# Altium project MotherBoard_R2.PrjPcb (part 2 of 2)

## Sheet powerSupplyAndMontior_r1.SchDoc
size A3; Date: Not shown in title block; ApprovedBy: Not shown in title block; CheckedBy: Not shown in title block; Author: Not shown in title block; CompanyName: Not shown in title block; Engineer: Not shown in title block; Organization: Not shown in title block; Address1: Not shown in title block; Address2: Not shown in title block; Address3: Not shown in title block; Address4: Not shown in title block; DocumentNumber: 2; Revision: Use project parameter SCH_Rev; SheetNumber: 2; SheetTotal: 3; PageSetup: Record=PageOptions¦CenterHorizontal=True¦CenterVertical=True¦PrintScale=1.00¦XCorrection=1.00¦YCorrection=1.00¦PrintKind=0¦BorderSize=5000000¦LeftOffset=0¦BottomOffset=0¦Orientation=2¦PaperLength=1000¦PaperWidth=1000¦Scale=100¦PaperSource=15¦PrintQuality=600¦MediaType=1¦DitherType=10¦PaperKind=Letter¦PrintScaleMode=1
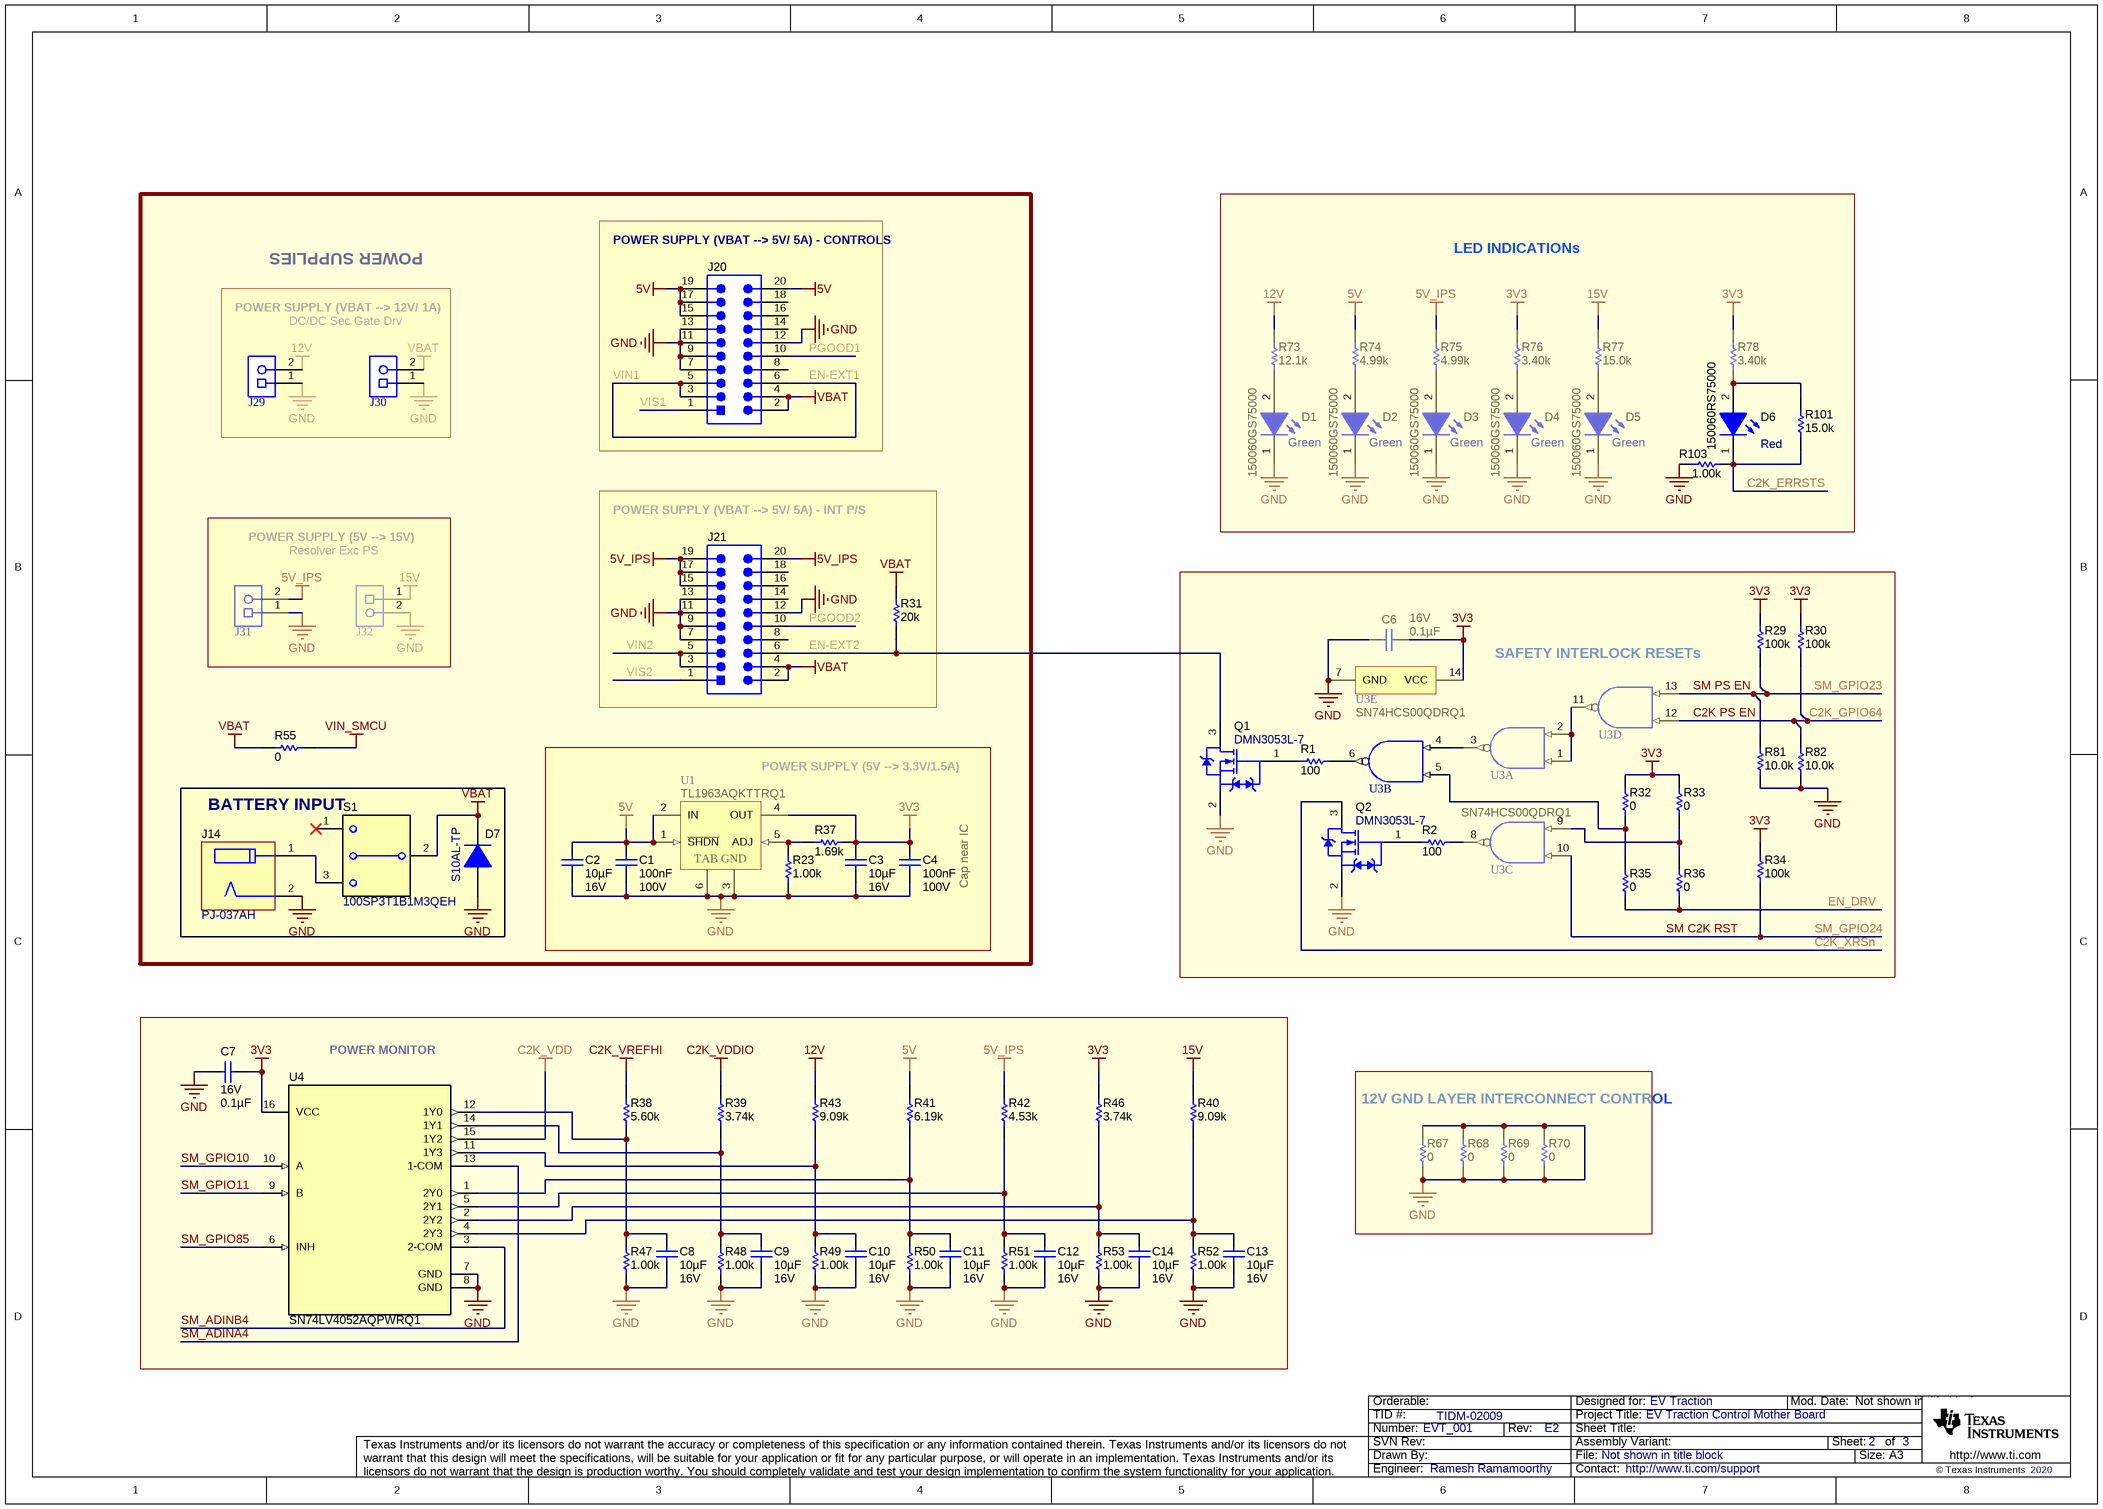
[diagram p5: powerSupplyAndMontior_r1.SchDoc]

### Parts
C1  Cap_F: 100nF  VDC_V: 100V  [0805_HV]  (hidden comment: C2012X7R2A104K125AA)
C2  ValueDisplayed: 10µF  VDC_V: 16V  [0805_HV]  (hidden comment: GRM21BR61C106KE15K)
C3  ValueDisplayed: 10µF  VDC_V: 16V  [0805_HV]  (hidden comment: GRM21BR61C106KE15K)
C4  Cap_F: 100nF  VDC_V: 100V  [0805_HV]  (hidden comment: C2012X7R2A104K125AA)
C6  VDC_V: 16V  ValueDisplayed: 0.1µF  [1206]  (hidden comment: 1206YC104KAT2A)
C7  VDC_V: 16V  ValueDisplayed: 0.1µF  [1206]  (hidden comment: 1206YC104KAT2A)
C8  ValueDisplayed: 10µF  VDC_V: 16V  [0805_HV]  (hidden comment: GRM21BR61C106KE15K)
C9  ValueDisplayed: 10µF  VDC_V: 16V  [0805_HV]  (hidden comment: GRM21BR61C106KE15K)
C10  ValueDisplayed: 10µF  VDC_V: 16V  [0805_HV]  (hidden comment: GRM21BR61C106KE15K)
C11  ValueDisplayed: 10µF  VDC_V: 16V  [0805_HV]  (hidden comment: GRM21BR61C106KE15K)
C12  ValueDisplayed: 10µF  VDC_V: 16V  [0805_HV]  (hidden comment: GRM21BR61C106KE15K)
C13  ValueDisplayed: 10µF  VDC_V: 16V  [0805_HV]  (hidden comment: GRM21BR61C106KE15K)
C14  ValueDisplayed: 10µF  VDC_V: 16V  [0805_HV]  (hidden comment: GRM21BR61C106KE15K)
D1  150060GS75000  value Green  [WL-SMCW_GREEN]
D2  150060GS75000  value Green  [WL-SMCW_GREEN]
D3  150060GS75000  value Green  [WL-SMCW_GREEN]
D4  150060GS75000  value Green  [WL-SMCW_GREEN]
D5  150060GS75000  value Green  [WL-SMCW_GREEN]
D6  150060RS75000  value Red  [WL-SMCW_RED]
D7  S10AL-TP  [SMC_265]
J14  PJ-037AH  [CUI_PJ-037AH]
J20  SBH11-PBPC-D10-ST-BK  [Sullins_SBH11-xxxC-D10-ST]  (value not drawn)
J21  SBH11-PBPC-D10-ST-BK  [Sullins_SBH11-xxxC-D10-ST]  (value not drawn)
J29  5-534206-1  [CONN_534206-1]  (value not drawn)
J30  5-534206-1  [CONN_534206-1]  (value not drawn)
J31  5-534206-1  [CONN_534206-1]  (value not drawn)
J32  5-534206-1  [CONN_534206-1]  (value not drawn)
Q1  DMN3053L-7  [SOT-23]
Q2  DMN3053L-7  [SOT-23]
R1  ValueDisplayed: 100  [0603]  (hidden comment: CRCW0603100RFKEA)
R2  ValueDisplayed: 100  [0603]  (hidden comment: CRCW0603100RFKEA)
R23  ValueDisplayed: 1.00k  [0805_HV]  (hidden comment: ERJ-P06F1001V)
R29  ValueDisplayed: 100k  [0805_HV]  (hidden comment: RT0805BRD07100KL)
R30  ValueDisplayed: 100k  [0805_HV]  (hidden comment: RT0805BRD07100KL)
R31  ValueDisplayed: 20k  [0805_HV]  (hidden comment: ERJ-6GEYJ203V)
R32  ValueDisplayed: 0  [0805_HV]  (hidden comment: ERJ-6GEY0R00V)
R33  ValueDisplayed: 0  [0805_HV]  (hidden comment: ERJ-6GEY0R00V)
R34  ValueDisplayed: 100k  [0805_HV]  (hidden comment: RT0805BRD07100KL)
R35  ValueDisplayed: 0  [0805_HV]  (hidden comment: ERJ-6GEY0R00V)
R36  ValueDisplayed: 0  [0805_HV]  (hidden comment: ERJ-6GEY0R00V)
R37  ValueDisplayed: 1.69k  [0805_HV]  (hidden comment: ERJ-6ENF1691V)
R38  ValueDisplayed: 5.60k  [0805_HV]  (hidden comment: RR1220P-562-D)
R39  ValueDisplayed: 3.74k  [0805_HV]  (hidden comment: RR1220P-3741-D-M)
R40  ValueDisplayed: 9.09k  [0805_HV]  (hidden comment: ERJ-6ENF9091V)
R41  ValueDisplayed: 6.19k  [0805_HV]  (hidden comment: ERJ-6ENF6191V)
R42  ValueDisplayed: 4.53k  [0805_HV]  (hidden comment: RR1220P-4531-D-M)
R43  ValueDisplayed: 9.09k  [0805_HV]  (hidden comment: ERJ-6ENF9091V)
R46  ValueDisplayed: 3.74k  [0805_HV]  (hidden comment: RR1220P-3741-D-M)
R47  ValueDisplayed: 1.00k  [0805_HV]  (hidden comment: ERJ-P06F1001V)
R48  ValueDisplayed: 1.00k  [0805_HV]  (hidden comment: ERJ-P06F1001V)
R49  ValueDisplayed: 1.00k  [0805_HV]  (hidden comment: ERJ-P06F1001V)
R50  ValueDisplayed: 1.00k  [0805_HV]  (hidden comment: ERJ-P06F1001V)
R51  ValueDisplayed: 1.00k  [0805_HV]  (hidden comment: ERJ-P06F1001V)
R52  ValueDisplayed: 1.00k  [0805_HV]  (hidden comment: ERJ-P06F1001V)
R53  ValueDisplayed: 1.00k  [0805_HV]  (hidden comment: ERJ-P06F1001V)
R55  ValueDisplayed: 0  [0805_HV]  (hidden comment: ERJ-6GEY0R00V)
R67  ValueDisplayed: 0  [0805_HV]  (hidden comment: ERJ-6GEY0R00V)
R68  ValueDisplayed: 0  [0805_HV]  (hidden comment: ERJ-6GEY0R00V)
R69  ValueDisplayed: 0  [0805_HV]  (hidden comment: ERJ-6GEY0R00V)
R70  ValueDisplayed: 0  [0805_HV]  (hidden comment: ERJ-6GEY0R00V)
R73  ValueDisplayed: 12.1k  [0805_HV]  (hidden comment: ERJ-6ENF1212V)
R74  ValueDisplayed: 4.99k  [0805_HV]  (hidden comment: ERJ-6ENF4991V)
R75  ValueDisplayed: 4.99k  [0805_HV]  (hidden comment: ERJ-6ENF4991V)
R76  ValueDisplayed: 3.40k  [0805_HV]  (hidden comment: ERJ-6ENF3401V)
R77  ValueDisplayed: 15.0k  [0805_HV]  (hidden comment: CRCW080515K0FKEA)
R78  ValueDisplayed: 3.40k  [0805_HV]  (hidden comment: ERJ-6ENF3401V)
R81  ValueDisplayed: 10.0k  [0805_HV]  (hidden comment: RR1220P-103-D)
R82  ValueDisplayed: 10.0k  [0805_HV]  (hidden comment: RR1220P-103-D)
R101  ValueDisplayed: 15.0k  [0805_HV]  (hidden comment: CRCW080515K0FKEA)
R103  ValueDisplayed: 1.00k  [0805_HV]  (hidden comment: ERJ-P06F1001V)
S1  100SP3T1B1M3QEH  [SW_100SP3T1B1M3QEH]
U1  TL1963AQKTTRQ1  [KTT0005A_N]
U3  SN74HC00QDRG4Q1  [D0014A_N]  (value not drawn)  (parts A,B,C,D,E of 5)
U4  SN74LV4052AQPWRQ1  [PW0016A_N]

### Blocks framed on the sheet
POWER SUPPLIES: C1-C4 J29-J32 R23 R37 R55 U1
POWER SUPPLY (VBAT --> 5V/ 5A) - CONTROLS: J20
LED INDICATIONs: D1-D6 R73-R78 R101 R103
POWER SUPPLY (VBAT --> 5V/ 5A) - INT P/S: J21 R31
SAFETY INTERLOCK RESETs: C6 Q1 Q2 R1 R2 R29 R30 R32-R36 R81 R82 U3
BATTERY INPUT: D7 J14 S1
POWER MONITOR: C7-C14 R38-R43 R46-R53 U4
12V GND LAYER INTERCONNECT CONTROL: R67-R70

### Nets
3V3: C3.2 C4.1 C6.2 C7.1 R29.2 R30.2 R32.2 R33.2 R34.2 R37.1 R46.2 R76.2 R78.2 U1.4(OUT) U3.14(VCC) U4.16(VCC)
5V: C1.1 C2.1 J20.15 J20.17 J20.19 J20.20 R41.2 R74.2 U1.1(~{SHDN}) U1.2(IN)
5V_IPS: J21.15 J21.17 J21.19 J21.20 J31.2 R42.2 R75.2
12V: J29.2 R43.2 R73.2
15V: J32.1 R40.2 R77.2
C2K_VDD: U4.15(1Y2)
C2K_VDDIO: R39.2
C2K_VREFHI: R38.2
GND: C1.2 C2.2 C3.1 C4.2 C6.1 C7.2 C8.1 C9.1 C10.1 C11.1 C12.1 C13.1 C14.1 D1.1(K) D2.1(K) D3.1(K) D4.1(K) D5.1(K) D7.2(A) J14.2 J20.7 J20.9 J20.11 J20.12 J20.13 J21.7 J21.9 J21.11 J21.12 J21.13 J29.1 J30.1 J31.1 J32.2 Q1.2(S) Q2.2(S) R23.1 R47.1 R48.1 R49.1 R50.1 R51.1 R52.1 R53.1 R67.1 R67.2 R68.1 R68.2 R69.1 R69.2 R70.1 R70.2 R81.1 R82.1 R103.2 U1.3(GND) U1.6(TAB) U3.7(GND) U4.7(GND) U4.8(GND)
VBAT: D7.1(K) J20.2 J20.4 J21.2 J21.4 J30.2 R31.2 R55.1 S1.2(COM)
VIN_SMCU: R55.2
C2K PS EN: R30.1 R82.2 U3.12(4A)  [also labelled C2K_GPIO64]
C2K_ERRSTS: D6.1(K) R101.1 R103.1
C2K_XRSn: Q2.3(D)
EN-EXT1: J20.3 J20.5 J20.6  [also labelled VIN1]
EN-EXT2: J21.6 Q1.3(D) R31.1
EN_DRV: R35.1 R36.1
PGOOD1: J20.10
PGOOD2: J21.10
SM C2K RST: R34.1 U3.10(3B)  [also labelled SM_GPIO24]
SM PS EN: R29.1 R81.2 U3.13(4B)  [also labelled SM_GPIO23]
SM_ADINA4: U4.13(1-COM)
SM_ADINB4: U4.3(2-COM)
SM_GPIO10: U4.10(A)
SM_GPIO11: U4.9(B)
SM_GPIO85: U4.6(INH)
VIN2: J21.3 J21.5
VIS1: J20.1
VIS2: J21.1
NetC8_2: C8.2 R38.1 R47.2 U4.12(1Y0)
NetC9_2: C9.2 R39.1 R48.2 U4.14(1Y1)
NetC10_2: C10.2 R43.1 R49.2 U4.11(1Y3)
NetC11_2: C11.2 R41.1 R50.2 U4.1(2Y0)
NetC12_2: C12.2 R42.1 R51.2 U4.5(2Y1)
NetC13_2: C13.2 R40.1 R52.2 U4.4(2Y3)
NetC14_2: C14.2 R46.1 R53.2 U4.2(2Y2)
NetD1_2: D1.2(A) R73.1
NetD2_2: D2.2(A) R74.1
NetD3_2: D3.2(A) R75.1
NetD4_2: D4.2(A) R76.1
NetD5_2: D5.2(A) R77.1
NetD6_2: D6.2(A) R78.1 R101.2
NetJ14_1: J14.1 S1.3
NetQ1_1: Q1.1(G) R1.1
NetQ2_1: Q2.1(G) R2.1
NetR1_2: R1.2 U3.6(2Y)
NetR2_2: R2.2 U3.8(3Y)
NetR23_2: R23.2 R37.2 U1.5(ADJ)
NetR32_1: R32.1 R35.2 U3.5(2B)
NetR33_1: R33.1 R36.2 U3.9(3A)
NetU3_1: U3.1(1A) U3.2(1B) U3.11(4Y)
NetU3_3: U3.3(1Y) U3.4(2A)

Not connected (* = marked no-connect by the designer): J20 8 14 16 18; J21 8 14 16 18; S1 1*

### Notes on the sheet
- POWER SUPPLY (VBAT --> 12V/ 1A)
- DC/DC Sec Gate Drv
- POWER SUPPLY (5V --> 15V)
- Resolver Exc PS
- (near U1) POWER SUPPLY (5V --> 3.3V/1.5A)
- (near C4) Cap near IC

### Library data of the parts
C1 C4 = CMP-0007886-2: CAP, CERM, 0.1 uF, 100 V, +/- 10%, X7R, 0805; Manufacturer: TDK; TaMin_C: -55°C; ESR_ohm: 0.020726; Polarized: N; SizeAreaWB_mm2: 6.75; Value1: 0.020726 ohm; U/M: EA; Value: 0.1uF; TaMax_C: 125°C; SizeZ_mm: 1.45; SizeX_mm: 2; SizeY_mm: 1.25; Cap_Case: 0805; SizeArea_mm2: 2.5; IRMS_A: 1.456A; AEC Category: Q200
C2 C3 C8-C14 = CMP-0086228-1: CAP, CERM, 10 µF, 16 V,+/- 10%, X5R, 0805; Manufacturer: MuRata; Green_REACh: Incomplete; TaMax_C: 85°C; Value: 10uF; Green_Lifecycle: Active; AEC Qualified: N; SizeY_mm: 1.25; SizeX_mm: 2; AEC Category: Q200; Cap_Case: 0805; SizeArea_mm2: 2.5; SizeAreaWB_mm2: 6.75; SizeZ_mm: 1.45; TaMin_C: -55°C; U/M: EA
C6 C7 = CMP-0860522-1: CAP, CERM, 0.1 µF, 16 V,+/- 10%, X7R, 1206; Manufacturer: AVX; SizeArea_mm2: 5.12; SizeX_mm: 3.2; Value: 0.1uF; SizeAreaWB_mm2: 10.92; Cap_F: 100nF; SizeZ_mm: 1.35; AEC Category: Q200; Polarized: N; U/M: EA; SizeY_mm: 1.6; TaMin_C: -55°C; TaMax_C: 125°C
D1-D5 = CMP-0002905-2: LED, Green, SMD; Manufacturer: Wurth Elektronik; Type: InGaN; Vf_V: 3.2V; Io_A: 20mA; Tjmax_C: 85°C; Value1: W; Angle: 140
D6 = CMP-0002947-3: LED, Red, SMD; Manufacturer: Wurth Elektronik; Value1: 0.072W; Vf_V: 2V; Angle: 140; Tjmax_C: 85°C; Type: AlInGaP; Vr_V: 5V; Io_A: 30mA; Power_TotalModule: 72mW
D7 = CMP-0077511-1: Diode, Standard Recovery Rectifier, 50 V, 10 A, SMC; Manufacturer: Micro Commercial Components; SizeAreaWB_mm2: 78.5757; Vr_V: 50V; SizeArea_mm2: 46.8857; AEC Qualified: N; AEC Category: Q101; Value: 50V; SizeZ_mm: 2.62; Io_A: 10A; Vf_V: 1.2V; SizeY_mm: 5.905; U/M: EA; SizeX_mm: 7.94
J14 = CMP-0075114-1: Power Jack, 2mm, R/A, TH; Manufacturer: CUI Inc.; CNHeader: False; Shrouded: N; Gender: Male; Row_Count: 1; Pitch_mm: 6
J20 J21 = CMP-0054720-2: Header (Shrouded), 2.54mm, 10x2, Gold, Black, TH; Manufacturer: Sullins Connector Solutions; Current_A: 3A; Green_Lifecycle: Not Set; Shrouded: Y; Gender: Male; Green_REACh: Incomplete; Voltage_V: 1kV; Row_Count: 2; RowSpacing_mm: 2.54
J29-J32 = CMP-0054836-1: Connector, Receptacle, 100mil, 2x1, Gold plated, TH; Manufacturer: TE Connectivity; CNHeader: FALSE; Green_Lifecycle: Active; Green_REACh: Passed
Q1 Q2 = CMP-0000613-1: MOSFET, N-CH, 30 V, 4 A, AEC-Q101, SOT-23; Alternate Manufacturer: None; Manufacturer: Diodes Inc.; SizeZ_mm: 1.1; ChType: N; Value2: 7.3 nC; Value1: 0; VdsMax_V: 30V; SizeX_mm: 2.5; SizeY_mm: 3; Vgs_V: 12V; AEC Qualified: Y; Value: 30V; Rdson45_ohm: 0.05; SizeArea_mm2: 7.5; AEC Category: Q101; IdsMax_A: 4A; SizeAreaWB_mm2: 14; U/M: EA; QgTyp_nC: 7.3
R1 R2 = CMP-0021991-4: RES, 100, 1%, 0.1 W, AEC-Q200 Grade 0, 0603; Manufacturer: Vishay-Dale; Power_W: 100mW; TempCo: 100 ppm/C; Value_Code: 100R; Value: 100; EIA_Code: E96; SizeX_mm: 1.6; SizeY_mm: 0.8; SizeZ_mm: 1; Value2: 0.1W; SizeArea_mm2: 1.28; AEC Qualified: Y; VDC_V: 75V; AEC Category: Q200; AEC Grade: 0
R23 R47-R53 R103 = CMP-0021848-2: RES, 1.00 k, 1%, 0.25 W, 0805; Manufacturer: Panasonic; Power_W: 250mW; TempCo: 100 ppm/C; Value_Code: 1k00; U/M: EA; Value: 1.00k; EIA_Code: E96; Res_ohm: 1k; SizeX_mm: 2; SizeY_mm: 1.25; SizeZ_mm: 1.45; Value2: 0.25W; SizeArea_mm2: 2.5; VDC_V: 400V; AEC Category: Q200
R29 R30 R34 = CMP-0019441-2: RES, 100 k, 0.1%, 0.125 W, 0805; Manufacturer: Yageo America; Power_W: 125mW; TempCo: 25 ppm/C; U/M: EA; Value: 100k; EIA_Code: E192; SizeX_mm: 2; SizeY_mm: 1.25; SizeZ_mm: 1.45; Value2: 0.125W; SizeArea_mm2: 2.5; VDC_V: 150V; AEC Category: Q200
R31 = CMP-0020671-1: RES, 20 k, 5%, 0.125 W, 0805; Manufacturer: Panasonic; Power_W: 125mW; TempCo: 200 ppm/C; Value_Code: 20k0; U/M: EA; Value: 20k; EIA_Code: E24; SizeX_mm: 2; SizeY_mm: 1.25; SizeZ_mm: 1.45; Value2: 0.125W; SizeArea_mm2: 2.5; VDC_V: 150V; AEC Category: Q200
R32 R33 R35 R36 R55 R67-R70 = CMP-0020616-3: RES, 0, 5%, 0.125 W, AEC-Q200 Grade 0, 0805; Manufacturer: Panasonic; Power_W: 125mW; TempCo: 600 ppm/C; Value_Code: 0000; Value: 0; EIA_Code: E24; SizeX_mm: 2; SizeY_mm: 1.25; SizeZ_mm: 1.45; Value2: 0.125W; SizeArea_mm2: 2.5; AEC Qualified: Y; VDC_V: 150V; AEC Category: Q200; SizeAreaWB_mm2: 6.75
R37 = CMP-0021591-3: RES, 1.69 k, 1%, 0.125 W, AEC-Q200 Grade 0, 0805; Manufacturer: Panasonic; Power_W: 125mW; TempCo: 100 ppm/C; Value_Code: 1k69; Value: 1.69k; EIA_Code: E96; SizeX_mm: 2; SizeY_mm: 1.25; SizeZ_mm: 1.45; Value2: 0.125W; SizeArea_mm2: 2.5; AEC Qualified: Y; AEC Category: Q200; AEC Grade: 0; SizeAreaWB_mm2: 6.75
R38 = CMP-0019324-1: RES, 5.60 k, 0.5%, 0.1 W, 0805; Manufacturer: Susumu Co Ltd; Power_W: 100mW; TempCo: 25 ppm/C; Value_Code: 5k60; U/M: EA; Value: 5.60k; Res_ohm: 5.6k; SizeX_mm: 2; SizeY_mm: 1.25; SizeZ_mm: 1.45; Value2: 0.1W; SizeArea_mm2: 2.5; VDC_V: 100V; AEC Category: Q200
R39 R46 = CMP-0019268-2: RES, 3.74 k, 0.5%, 0.1 W, 0805; Manufacturer: Susumu Co Ltd; Power_W: 100mW; TempCo: 25 ppm/C; Value_Code: 3k74; U/M: EA; Value: 3.74k; EIA_Code: E192; SizeX_mm: 2; SizeY_mm: 1.25; SizeZ_mm: 1.45; Value2: 0.1W; SizeArea_mm2: 2.5; VDC_V: 100V; AEC Category: Q200
R40 R43 = CMP-0021809-3: RES, 9.09 k, 1%, 0.125 W, AEC-Q200 Grade 0, 0805; Manufacturer: Panasonic; Power_W: 125mW; TempCo: 100 ppm/C; Value_Code: 9k09; Value: 9.09k; EIA_Code: E96; SizeX_mm: 2; SizeY_mm: 1.25; SizeZ_mm: 1.45; Value2: 0.125W; SizeArea_mm2: 2.5; AEC Qualified: Y; AEC Category: Q200; AEC Grade: 0; SizeAreaWB_mm2: 6.75
R41 = CMP-0021761-3: RES, 6.19 k, 1%, 0.125 W, AEC-Q200 Grade 0, 0805; Manufacturer: Panasonic; Value: 6.19k; EIA_Code: E96; SizeX_mm: 2; SizeY_mm: 1.25; SizeZ_mm: 1.45; Value2: 0.125W; SizeArea_mm2: 2.5; AEC Qualified: Y; AEC Category: Q200; AEC Grade: 0; Power_W: 125mW; TempCo: 100 ppm/C; Value_Code: 6k19; SizeAreaWB_mm2: 6.75
R42 = CMP-0019292-2: RES, 4.53 k, 0.5%, 0.1 W, 0805; Manufacturer: Susumu Co Ltd; Power_W: 100mW; TempCo: 25 ppm/C; Value_Code: 4k53; U/M: EA; Value: 4.53k; EIA_Code: E192; SizeX_mm: 2; SizeY_mm: 1.25; SizeZ_mm: 1.45; Value2: 0.1W; SizeArea_mm2: 2.5; VDC_V: 100V; AEC Category: Q200
R73 = CMP-0021547-3: RES, 12.1 k, 1%, 0.125 W, AEC-Q200 Grade 0, 0805; Manufacturer: Panasonic; Power_W: 125mW; TempCo: 100 ppm/C; Value_Code: 12k1; Value: 12.1k; EIA_Code: E96; SizeX_mm: 2; SizeY_mm: 1.25; SizeZ_mm: 1.45; Value2: 0.125W; SizeArea_mm2: 2.5; AEC Qualified: Y; AEC Category: Q200; AEC Grade: 0; SizeAreaWB_mm2: 6.75
R74 R75 = CMP-0021733-3: RES, 4.99 k, 1%, 0.125 W, AEC-Q200 Grade 0, 0805; Manufacturer: Panasonic; Power_W: 125mW; TempCo: 100 ppm/C; Value_Code: 4k99; Value: 4.99k; EIA_Code: E96; SizeX_mm: 2; SizeY_mm: 1.25; SizeZ_mm: 1.45; Value2: 0.125W; SizeArea_mm2: 2.5; AEC Qualified: Y; AEC Category: Q200; AEC Grade: 0; SizeAreaWB_mm2: 6.75
R76 R78 = CMP-0021683-3: RES, 3.40 k, 1%, 0.125 W, AEC-Q200 Grade 0, 0805; Manufacturer: Panasonic; Power_W: 125mW; TempCo: 100 ppm/C; Value_Code: 3k40; Value: 3.40k; EIA_Code: E96; Res_ohm: 3.4k; SizeX_mm: 2; SizeY_mm: 1.25; SizeZ_mm: 1.45; Value2: 0.125W; SizeArea_mm2: 2.5; AEC Qualified: Y; AEC Category: Q200; AEC Grade: 0; SizeAreaWB_mm2: 6.75
R77 R101 = CMP-0020909-2: RES, 15.0 k, 1%, 0.125 W, 0805; Manufacturer: Vishay-Dale; Power_W: 125mW; TempCo: 100 ppm/C; Value_Code: 15k0; U/M: EA; Value: 15.0k; EIA_Code: E96; Res_ohm: 15k; SizeX_mm: 2; SizeY_mm: 1.25; SizeZ_mm: 1.45; Value2: 0.125W; SizeArea_mm2: 2.5; VDC_V: 150V; AEC Category: Q200
R81 R82 = CMP-0019095-2: RES, 10.0 k, 0.5%, 0.1 W, 0805; Manufacturer: Susumu Co Ltd; Power_W: 100mW; TempCo: 25 ppm/C; Value_Code: 10k0; U/M: EA; Value: 10.0k; EIA_Code: E192; Res_ohm: 10k; SizeX_mm: 2; SizeY_mm: 1.25; SizeZ_mm: 1.45; Value2: 0.1W; SizeArea_mm2: 2.5; VDC_V: 100V; AEC Category: Q200
S1 = CMP-0002236-1: Switch, Toggle SPDT 5A, 120V, TH; Manufacturer: E-Switch; CurrentRating_mA: 5kA; PositionCount: 3; VDC_V: 28V; SwitchFunction: ON-OFF-ON
U1 = CMP-0036893-1: Single Output Fast Transient Response LDO, 1.5 A, Adjustable 1.21 to 20 V Output, 2.1 to 20 V Input, 5-pin DDPAK (KTT), -40 to 125 degC, Green (RoHS & no Sb/Br); Manufacturer: Texas Instruments; Vin(Min)(V): 2.1; SubFamily: Single Channel LDO; Vdo(Typ)(mV): 340; Iq(Typ)(mA): 1; Vout Adj(Min)(V): 1.21; Vin(Max)(V): 20; Iout(Max)(A): 1.5
U3 = CMP-0052992-1: Automotive Catalog Quad 2-Input Positive-NAND Gates, D0014A, LARGE T&R; PartNumber: SN74HCS00QDRQ1; Manufacturer: Texas Instruments; Technology Family: HC; Input Type: CMOS; Schmitt Trigger: No; Output Drive (IOL/IOH)(Max)(mA): 5.2/-5.2; F @ Nom Voltage(Max)(Mhz): 70; ICC @ Nom Voltage(Max)(mA): 0.02; Bits(#): 4; Voltage(Nom)(V): 5; VCC(Min)(V): 2; VCC(Max)(V): 6; tpd @ Nom Voltage(Max)(ns): 23
U4 = CMP-0066257-1: Automotive Catalog Dual 4-Channel Analog Multiplexer/Demultiplexer, PW0016A (TSSOP-16); Alternate Manufacturer: Texas Instruments; SizeAreaWB_mm2: 58.8; U/M: EA; SizeZ_mm: 1.2; SizeX_mm: 6.4; SizeY_mm: 5.0; SizeArea_mm2: 32.0; CompType: IC

## Sheet ChildBoardComms_r3.SchDoc
size 431 x 279 mm; Date: Not shown in title block; ApprovedBy: Not shown in title block; CheckedBy: Not shown in title block; Author: Not shown in title block; CompanyName: Not shown in title block; Engineer: Not shown in title block; Organization: Not shown in title block; Address1: Not shown in title block; Address2: Not shown in title block; Address3: Not shown in title block; Address4: Not shown in title block; DocumentNumber: 2; Revision: Use project parameter SCH_Rev; SheetNumber: 2; SheetTotal: 3; PageSetup: Record=PageOptions¦CenterHorizontal=True¦CenterVertical=True¦PrintScale=1.00¦XCorrection=1.00¦YCorrection=1.00¦PrintKind=0¦BorderSize=5000000¦LeftOffset=0¦BottomOffset=0¦Orientation=2¦PaperLength=1000¦PaperWidth=1000¦Scale=100¦PaperSource=15¦PrintQuality=600¦MediaType=1¦DitherType=10¦PaperKind=Letter¦PrintScaleMode=1
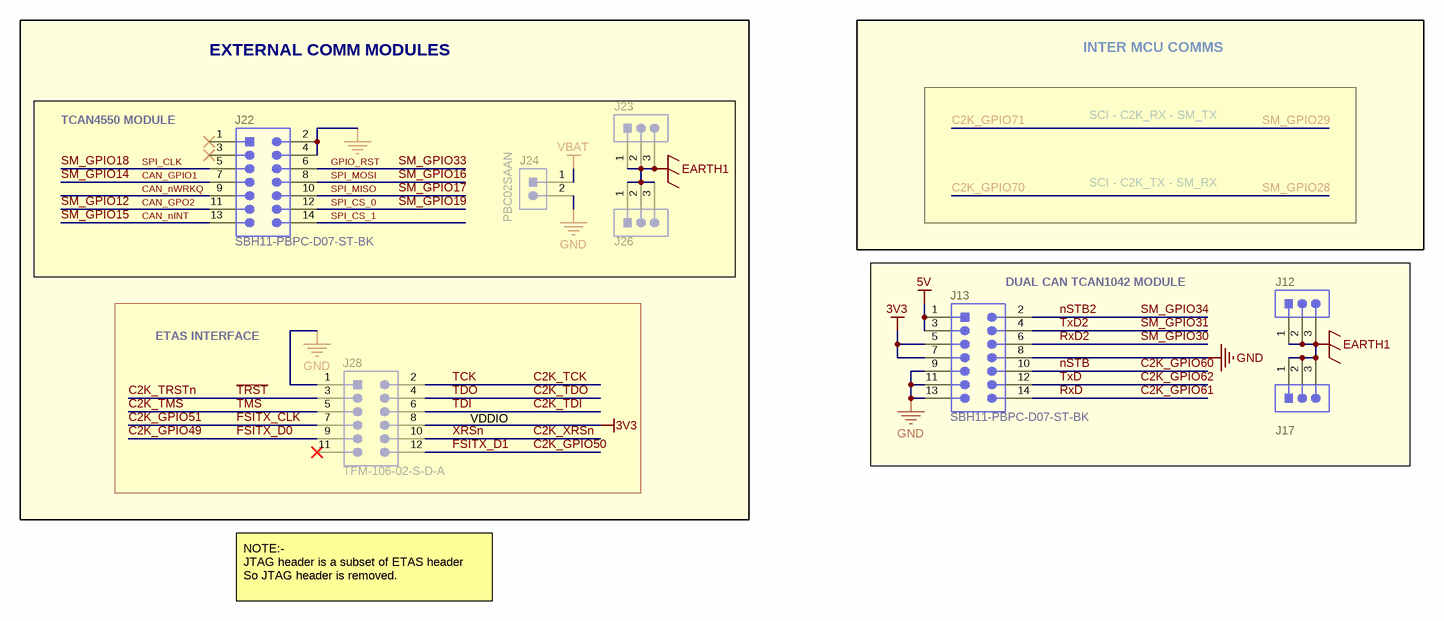
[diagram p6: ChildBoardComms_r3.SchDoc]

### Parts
J12  61300311121  [WURTH_61300311121]  (value not drawn)
J13  SBH11-PBPC-D07-ST-BK  [CONN_SBH11-PBPC-D07-ST-BK]
J17  61300311121  [WURTH_61300311121]  (value not drawn)
J22  SBH11-PBPC-D07-ST-BK  [CONN_SBH11-PBPC-D07-ST-BK]
J23  61300311121  [WURTH_61300311121]  (value not drawn)
J24  PBC02SAAN  [Sullins_PBC02SAAN]
J26  61300311121  [WURTH_61300311121]  (value not drawn)
J28  TFM-106-02-S-D-A  [Samtec_TFM-106-02-x-D-A]

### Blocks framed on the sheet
EXTERNAL COMM MODULES: J28
TCAN4550 MODULE: J22-J24 J26
DUAL CAN TCAN1042 MODULE: J12 J13 J17

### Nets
3V3: J13.5 J13.7 J28.8
5V: J13.1 J13.3
EARTH1: J12.1 J12.2 J12.3 J17.1 J17.2 J17.3 J23.1 J23.2 J23.3 J26.1 J26.2 J26.3
GND: J13.8 J13.9 J13.11 J13.13 J22.2 J22.4 J24.2 J28.1
VBAT: J24.1
C2K_GPIO49: J28.9  [also labelled FSITX_D0]
C2K_GPIO50: J28.12  [also labelled FSITX_D1]
C2K_GPIO51: J28.7  [also labelled FSITX_CLK]
C2K_GPIO60: J13.10  [also labelled nSTB]
C2K_GPIO61: J13.14  [also labelled RxD]
C2K_GPIO62: J13.12  [also labelled TxD]
C2K_TCK: J28.2  [also labelled TCK]
C2K_TDI: J28.6  [also labelled TDI]
C2K_TDO: J28.4  [also labelled TDO]
C2K_TMS: J28.5  [also labelled TMS]
C2K_TRSTn: J28.3  [also labelled ~{TRST}]
C2K_XRSn: J28.10  [also labelled XRSn]
CAN_GPIO1: J22.7  [also labelled SM_GPIO14]
CAN_GPO2: J22.11  [also labelled SM_GPIO12]
CAN_nINT: J22.13  [also labelled SM_GPIO15]
CAN_nWRKQ: J22.9
GPIO_RST: J22.6  [also labelled SM_GPIO33]
nSTB2: J13.2  [also labelled SM_GPIO34]
RxD2: J13.6  [also labelled SM_GPIO30]
SM_GPIO16: J22.8  [also labelled SPI_MOSI]
SM_GPIO17: J22.10  [also labelled SPI_MISO]
SM_GPIO18: J22.5  [also labelled SPI_CLK]
SM_GPIO19: J22.12  [also labelled SPI_CS_0]
SM_GPIO31: J13.4  [also labelled TxD2]
SPI_CS_1: J22.14

Not connected (* = marked no-connect by the designer): J22 1* 3*; J28 11*

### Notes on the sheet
- INTER MCU COMMS
- SCI - C2K_RX - SM_TX
- SCI - C2K_TX - SM_RX
- ETAS INTERFACE
- VDDIO
- NOTE:-
  JTAG header is a subset of ETAS header
  So JTAG header is removed.

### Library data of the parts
J12 J17 J23 J26 = CMP-0054796-2: Header, 2.54 mm, 3x1, Gold, TH; Manufacturer: Wurth Elektronik; Pitch_mm: 2.54; Green_Lifecycle: Active; Cert_UL: Y; Shrouded: N; Green_REACh: Passed; Gender: Male; Row_Count: 1
J13 J22 = CMP-0054695-2: Header (shrouded), 100 mil, 7x2, Gold, TH; Manufacturer: Sullins Connector Solutions; Green_REACh: Incomplete; Green_Lifecycle: Not Set
J24 = CMP-0054566-1: Header, 100mil, 2x1, Gold, TH; Manufacturer: Sullins Connector Solutions; CNHeader: TRUE; Current_A: 3A; Green_Lifecycle: Active; Shrouded: N; Gender: Male; Green_REACh: Passed; Voltage_V: 1.8kV; Row_Count: 1; Pitch_mm: 2.54; CT: FALSE; Cert_UL: Y
J28 = CMP-0075601-1: Header(Shrouded), 1.27mm, 6x2, Tin, SMT; Manufacturer: Samtec; Pitch_mm: 1.27; Gender: Male; Cert_CSA: Y; Current_A: 3.2A; Voltage_V: 250V; ContactFinish: Gold; CT: False; Row_Count: 2

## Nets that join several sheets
3V3: ChildBoardMotor_r2 (19 pins), ChildBoardDC-DC_r2 (7 pins), powerSupplyAndMontior_r1 (16 pins), ChildBoardComms_r3 (J13.5 J13.7 J28.8)
5V: ChildBoardMotor_r2 (J25.5 R79.1), MotherBoard_r2 (6 pins), ChildBoardDC-DC_r2 (J7.3 J7.4), powerSupplyAndMontior_r1 (10 pins), ChildBoardComms_r3 (J13.1 J13.3)
5V_IPS: ChildBoardMotor_r2 (6 pins), ChildBoardDC-DC_r2 (J7.7 J7.8), powerSupplyAndMontior_r1 (7 pins)
12V: ChildBoardDC-DC_r2 (J7.11 J7.12), powerSupplyAndMontior_r1 (J29.2 R43.2 R73.2)
15V: ChildBoardMotor_r2 (J9.1), powerSupplyAndMontior_r1 (J32.1 R40.2 R77.2)
C2K_VDD: MotherBoard_r2 (J1.118 TP3.1), powerSupplyAndMontior_r1 (U4.15)
C2K_VDDIO: MotherBoard_r2 (J1.119 TP4.1), powerSupplyAndMontior_r1 (R39.2)
C2K_VREFHI: MotherBoard_r2 (J1.45), powerSupplyAndMontior_r1 (R38.2)
EARTH: Hardware (H2.1), ChildBoardMotor_r2 (J10.1 J10.2 J10.3)
EARTH1: Hardware (H3.1), ChildBoardComms_r3 (12 pins)
GND: ChildBoardMotor_r2 (39 pins), MotherBoard_r2 (39 pins), ChildBoardDC-DC_r2 (26 pins), powerSupplyAndMontior_r1 (60 pins), ChildBoardComms_r3 (8 pins)
VBAT: ChildBoardMotor_r2 (C20.1 C21.1 C22.1 U7.11), powerSupplyAndMontior_r1 (9 pins), ChildBoardComms_r3 (J24.1)
VIN_SMCU: MotherBoard_r2 (5 pins), powerSupplyAndMontior_r1 (R55.2)
C2K PS EN: MotherBoard_r2 (J19.129), powerSupplyAndMontior_r1 (R30.1 R82.2 U3.12)
C2K_ADC-A2: ChildBoardMotor_r2 (J27.2), MotherBoard_r2 (J1.15 J2.57)
C2K_ADC-A3: ChildBoardMotor_r2 (J9.7), MotherBoard_r2 (J1.17)
C2K_ADC-A4: ChildBoardMotor_r2 (J27.3), MotherBoard_r2 (J1.21 J2.59)
C2K_ADC-A5: MotherBoard_r2 (J1.23), ChildBoardDC-DC_r2 (J5.4)
C2K_ADC-B0: MotherBoard_r2 (J1.12 J2.19), ChildBoardDC-DC_r2 (J5.10)
C2K_ADC-B1: ChildBoardMotor_r2 (R5.1), MotherBoard_r2 (J1.14)
C2K_ADC-B2: MotherBoard_r2 (J1.18), ChildBoardDC-DC_r2 (R56.2 R59.2)
C2K_ADC-B3: MotherBoard_r2 (J1.20), ChildBoardDC-DC_r2 (R58.2)
C2K_ADC-B4: ChildBoardMotor_r2 (J9.5), MotherBoard_r2 (J1.24 J2.61)
C2K_ADC-B5: MotherBoard_r2 (J1.26), ChildBoardDC-DC_r2 (J5.3)
C2K_ADC-C2: ChildBoardMotor_r2 (J27.5), MotherBoard_r2 (J1.31 J2.9)
C2K_ADC-C3: ChildBoardMotor_r2 (J27.1), MotherBoard_r2 (J1.33 J2.17)
C2K_ADC-C4: ChildBoardMotor_r2 (J9.6), MotherBoard_r2 (J1.37 J2.11)
C2K_ADC-C5: ChildBoardMotor_r2 (J9.8), MotherBoard_r2 (J1.39 J2.13)
C2K_ADC-D0: ChildBoardMotor_r2 (J27.4), MotherBoard_r2 (J1.28 J2.7)
C2K_ADC-D2: MotherBoard_r2 (J1.34 J2.21), ChildBoardDC-DC_r2 (J5.8)
C2K_ADC-D3: ChildBoardMotor_r2 (C24.2 J18.2 R102.2), MotherBoard_r2 (J1.36)
C2K_ADC-D5: ChildBoardMotor_r2 (J9.10), MotherBoard_r2 (J1.42 J2.63)
C2K_ADCIN14: MotherBoard_r2 (J1.25), ChildBoardDC-DC_r2 (C17.1 R60.2 R83.1)
C2K_ERRSTS: MotherBoard_r2 (J2.32 J19.178 TP5.1), powerSupplyAndMontior_r1 (D6.1 R101.1 R103.1)
C2K_GPIO0: ChildBoardMotor_r2 (J3.9), MotherBoard_r2 (J1.49)
C2K_GPIO1: ChildBoardMotor_r2 (J3.11), MotherBoard_r2 (J1.51)
C2K_GPIO2: ChildBoardMotor_r2 (J3.12), MotherBoard_r2 (J1.53)
C2K_GPIO3: ChildBoardMotor_r2 (J3.13), MotherBoard_r2 (J1.55)
C2K_GPIO4: ChildBoardMotor_r2 (J3.16), MotherBoard_r2 (J1.50)
C2K_GPIO5: ChildBoardMotor_r2 (J3.14), MotherBoard_r2 (J1.52)
C2K_GPIO6: MotherBoard_r2 (J1.54), ChildBoardDC-DC_r2 (J5.16)
C2K_GPIO7: MotherBoard_r2 (J1.56), ChildBoardDC-DC_r2 (J5.18)
C2K_GPIO8: MotherBoard_r2 (J1.57), ChildBoardDC-DC_r2 (J5.20)
C2K_GPIO9: MotherBoard_r2 (J1.59), ChildBoardDC-DC_r2 (J5.22)
C2K_GPIO10: MotherBoard_r2 (J1.61), ChildBoardDC-DC_r2 (J5.24)
C2K_GPIO11: MotherBoard_r2 (J1.63), ChildBoardDC-DC_r2 (R65.2)
C2K_GPIO12: MotherBoard_r2 (J1.58), ChildBoardDC-DC_r2 (R63.2)
C2K_GPIO13: MotherBoard_r2 (J1.60), ChildBoardDC-DC_r2 (R71.1)
C2K_GPIO14: ChildBoardMotor_r2 (R4.1), MotherBoard_r2 (J1.62)
C2K_GPIO24: ChildBoardMotor_r2 (J3.15), MotherBoard_r2 (J1.75)
C2K_GPIO25: ChildBoardMotor_r2 (J3.19), MotherBoard_r2 (J1.77)
C2K_GPIO26: ChildBoardMotor_r2 (J3.17), MotherBoard_r2 (J1.79)
C2K_GPIO27: ChildBoardMotor_r2 (J3.18), MotherBoard_r2 (J1.81)
C2K_GPIO29: ChildBoardMotor_r2 (U7.1 U7.2), MotherBoard_r2 (J1.78)
C2K_GPIO41: ChildBoardMotor_r2 (J9.14), MotherBoard_r2 (J1.91)
C2K_GPIO48: ChildBoardMotor_r2 (J6.5), MotherBoard_r2 (J1.99 J2.80)
C2K_GPIO49: MotherBoard_r2 (J1.101), ChildBoardComms_r3 (J28.9)
C2K_GPIO50: MotherBoard_r2 (J1.103), ChildBoardComms_r3 (J28.12)
C2K_GPIO51: MotherBoard_r2 (J1.105), ChildBoardComms_r3 (J28.7)
C2K_GPIO52: ChildBoardMotor_r2 (J9.12), MotherBoard_r2 (J1.107)
C2K_GPIO53: ChildBoardMotor_r2 (J9.3), MotherBoard_r2 (J1.109)
C2K_GPIO54: ChildBoardMotor_r2 (J25.4), MotherBoard_r2 (J1.100)
C2K_GPIO55: ChildBoardMotor_r2 (J25.3), MotherBoard_r2 (J1.102)
C2K_GPIO56: ChildBoardMotor_r2 (J25.2), MotherBoard_r2 (J1.104)
C2K_GPIO57: ChildBoardMotor_r2 (J25.1), MotherBoard_r2 (J1.106)
C2K_GPIO60: MotherBoard_r2 (J19.125), ChildBoardComms_r3 (J13.10)
C2K_GPIO61: MotherBoard_r2 (J19.126), ChildBoardComms_r3 (J13.14)
C2K_GPIO62: MotherBoard_r2 (J19.127), ChildBoardComms_r3 (J13.12)
C2K_GPIO66: ChildBoardMotor_r2 (R85.1), MotherBoard_r2 (J19.131)
C2K_GPIO68: ChildBoardMotor_r2 (J27.10 R21.2), MotherBoard_r2 (J19.133)
C2K_GPIO74: ChildBoardMotor_r2 (J6.6 R20.2), MotherBoard_r2 (J19.141)
C2K_GPIO78: ChildBoardMotor_r2 (J27.12), MotherBoard_r2 (J2.25 J19.145)
C2K_GPIO82: ChildBoardMotor_r2 (J27.14), MotherBoard_r2 (J2.75 J19.149)
C2K_GPIO86: ChildBoardMotor_r2 (R14.1), MotherBoard_r2 (J19.153)
C2K_GPIO88: ChildBoardMotor_r2 (R18.1), MotherBoard_r2 (J19.155)
C2K_GPIO90: ChildBoardMotor_r2 (R16.1), MotherBoard_r2 (J19.159)
C2K_GPIO92: ChildBoardMotor_r2 (R12.1), MotherBoard_r2 (J19.161)
C2K_GPIO94: ChildBoardMotor_r2 (R10.1), MotherBoard_r2 (J19.163)
C2K_GPIO96: ChildBoardMotor_r2 (J6.7), MotherBoard_r2 (J1.93 J2.85)
C2K_GPIO98: ChildBoardMotor_r2 (J6.8), MotherBoard_r2 (J1.95 J2.30)
C2K_GPIO127: ChildBoardMotor_r2 (R6.1), MotherBoard_r2 (J19.165)
C2K_GPIO147: ChildBoardMotor_r2 (R8.1), MotherBoard_r2 (J19.167)
C2K_TCK: MotherBoard_r2 (J1.5), ChildBoardComms_r3 (J28.2)
C2K_TDI: MotherBoard_r2 (J1.8), ChildBoardComms_r3 (J28.6)
C2K_TDO: MotherBoard_r2 (J1.6), ChildBoardComms_r3 (J28.4)
C2K_TMS: MotherBoard_r2 (J1.3), ChildBoardComms_r3 (J28.5)
C2K_TRSTn: MotherBoard_r2 (J1.4), ChildBoardComms_r3 (J28.3)
C2K_XRSn: MotherBoard_r2 (J1.120), powerSupplyAndMontior_r1 (Q2.3), ChildBoardComms_r3 (J28.10)
CAN_GPIO1: MotherBoard_r2 (J2.84), ChildBoardComms_r3 (J22.7)
CAN_GPO2: MotherBoard_r2 (J2.33), ChildBoardComms_r3 (J22.11)
CAN_nINT: MotherBoard_r2 (J2.34), ChildBoardComms_r3 (J22.13)
EN_DRV: ChildBoardMotor_r2 (R54.2), MotherBoard_r2 (J2.42 TP6.1), ChildBoardDC-DC_r2 (U6.2), powerSupplyAndMontior_r1 (R35.1 R36.1)
GPIO_RST: MotherBoard_r2 (J2.95), ChildBoardComms_r3 (J22.6)
nSTB2: MotherBoard_r2 (J2.46), ChildBoardComms_r3 (J13.2)
RxD2: MotherBoard_r2 (J2.44), ChildBoardComms_r3 (J13.6)
SM C2K RST: MotherBoard_r2 (J2.35), powerSupplyAndMontior_r1 (R34.1 U3.10)
SM PS EN: MotherBoard_r2 (J2.91), powerSupplyAndMontior_r1 (R29.1 R81.2 U3.13)
SM_ADINA4: MotherBoard_r2 (J2.65), powerSupplyAndMontior_r1 (U4.13)
SM_ADINB4: MotherBoard_r2 (J2.15), powerSupplyAndMontior_r1 (U4.3)
SM_GPIO0: ChildBoardMotor_r2 (R7.2), MotherBoard_r2 (J2.23)
SM_GPIO1: ChildBoardMotor_r2 (R13.2), MotherBoard_r2 (J2.73)
SM_GPIO2: ChildBoardMotor_r2 (R9.2), MotherBoard_r2 (J2.24)
SM_GPIO3: ChildBoardMotor_r2 (R11.2), MotherBoard_r2 (J2.74)
SM_GPIO6: ChildBoardMotor_r2 (R20.1 R21.1), MotherBoard_r2 (J2.26)
SM_GPIO7: ChildBoardMotor_r2 (U2.13), MotherBoard_r2 (J2.76)
SM_GPIO8: ChildBoardMotor_r2 (U2.1), MotherBoard_r2 (J2.28)
SM_GPIO9: ChildBoardMotor_r2 (U2.3), MotherBoard_r2 (J2.78)
SM_GPIO10: MotherBoard_r2 (J2.29), powerSupplyAndMontior_r1 (U4.10)
SM_GPIO11: MotherBoard_r2 (J2.79), powerSupplyAndMontior_r1 (U4.9)
SM_GPIO16: MotherBoard_r2 (J2.38), ChildBoardComms_r3 (J22.8)
SM_GPIO17: MotherBoard_r2 (J2.88), ChildBoardComms_r3 (J22.10)
SM_GPIO18: MotherBoard_r2 (J2.39), ChildBoardComms_r3 (J22.5)
SM_GPIO19: MotherBoard_r2 (J2.89), ChildBoardComms_r3 (J22.12)
SM_GPIO31: MotherBoard_r2 (J2.94), ChildBoardComms_r3 (J13.4)
SM_GPIO59: MotherBoard_r2 (J2.68), ChildBoardDC-DC_r2 (R72.1)
SM_GPIO60: ChildBoardMotor_r2 (R86.1), MotherBoard_r2 (J2.20)
SM_GPIO85: MotherBoard_r2 (J2.81), powerSupplyAndMontior_r1 (U4.6)
Vdc2_N: ChildBoardMotor_r2 (J16.4), ChildBoardDC-DC_r2 (J5.2)
Vdc2_P: ChildBoardMotor_r2 (J16.3), ChildBoardDC-DC_r2 (J5.1)

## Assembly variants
001: not fitted FID1 FID2 FID3 R5 R7 R9 R11 R13 R15 R17 R19 R21 R22 R24 R28 R35 R36 R44 R54 R56 R71 R79 R93 R94 R95 R99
